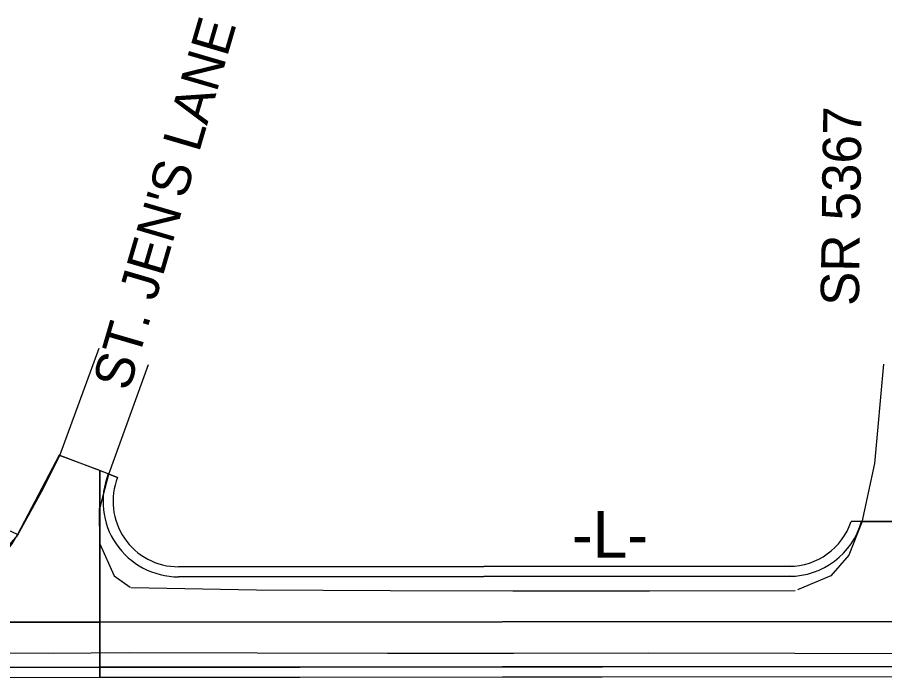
# Model space of a CAD drawing. Extents: x 2105791 to 2114488, y 667759 to 673441.
# Drawn here: x 2112480 to 2113084, y 670501 to 670961 of the extents above; entities that cross this region are included whole.
import ezdxf

# ---------------------------------------------------------------- set-up
doc = ezdxf.new("R2010")
doc.units = 0
for name, color, linetype in [('Exist Roads EOP', 7, 'Continuous'), ('Old_Level_1', 7, 'Continuous'), ('Prop EOT', 7, 'Continuous'), ('Prop Horizontal Alignment', 7, 'Continuous'), ('Prop Paved Shoulder', 7, 'Continuous'), ('Prop Shade Light', 7, 'Continuous')]:
    doc.layers.add(name, color=color, linetype=linetype)

msp = doc.modelspace()

# ---------------------------------------------------------------- linework, layer by layer
at = {"layer": 'Exist Roads EOP'}
for points in [[(2112536.43, 670730.29), (2112508.84, 670655.53), (2112496.29, 670630.73), (2112479.68, 670600.25), (2112452.98, 670569.69), (2112441.53, 670562.44)], [(2112570.66, 670719.08), (2112543.07, 670642.63), (2112536.77, 670618.71), (2112537.07, 670594.37), (2112546.95, 670571.87), (2112558.04, 670564.12)], [(2113083.05, 670719.57), (2113076.75, 670650.17), (2113067.96, 670609.35), (2113058.84, 670586.27), (2113046.36, 670571.99), (2113023.17, 670562.21)], [(2112558.52, 670563.78), (2112646.2, 670562.17), (2112739.32, 670561.73), (2112824.81, 670561.53), (2112919.99, 670561.59), (2113021.45, 670561.81)], [(2112231.19, 670513.92), (2112247.63, 670517.75), (2112319.83, 670518.16), (2112407.44, 670518.23), (2112504.55, 670518.1), (2112557.45, 670518.47), (2112646.65, 670518.39), (2112737.56, 670518.17), (2112825.34, 670518.17), (2112919.34, 670518.21), (2113021.28, 670518.03), (2113096.8, 670517.86), (2113173.07, 670517.66)]]:
    msp.add_lwpolyline(points, dxfattribs=at)
at = {"layer": 'Prop EOT'}
for p, q in [((2112508.7, 670656.04), (2112479.54, 670600.77)), ((2112542.92, 670643.14), (2112508.7, 670656.04)), ((2113067.82, 670609.84), (2113132.62, 670609.89)), ((2112591.77, 670571.28), (2113017.34, 670571.62)), ((2112229.9, 670507.99), (2113182.43, 670508.76))]:
    msp.add_line(p, q, dxfattribs=at)
for centre, start, end in [((2112591.73, 670623.78), 158.36737, 270.04585), ((2113017.3, 670624.12), 270.04586, 344.21029), ((2112432.29, 670623.66), 270.04586, 334.15022)]:
    msp.add_arc(centre, 52.5, start, end, dxfattribs=at)
at = {"layer": 'Prop Horizontal Alignment'}
msp.add_line((2111105.82, 670538.59), (2114200.25, 670541.07), dxfattribs=at)
at = {"layer": 'Prop Paved Shoulder'}
for p, q in [((2112542.92, 670643.14), (2112549.43, 670640.56)), ((2113067.82, 670609.84), (2113060.49, 670609.83)), ((2112479.54, 670600.77), (2112473.24, 670603.82)), ((2112591.76, 670578.28), (2113017.33, 670578.62)), ((2112229.91, 670500.99), (2113812.44, 670502.26))]:
    msp.add_line(p, q, dxfattribs=at)
for centre, start, end in [((2112591.73, 670623.78), 158.36737, 270.04585), ((2113017.3, 670624.12), 270.04586, 341.69358)]:
    msp.add_arc(centre, 45.5, start, end, dxfattribs=at)
at = {"layer": 'Prop Shade Light'}
for p, q in [((2112508.99, 670655.93), (2112508.84, 670655.53)), ((2112508.99, 670655.93), (2112508.84, 670655.53)), ((2112537.13, 670645.32), (2112508.99, 670655.93)), ((2112537.13, 670645.32), (2112508.99, 670655.93)), ((2112542.92, 670643.14), (2112537.13, 670645.32)), ((2112537.13, 670645.32), (2112537.13, 670539.74)), ((2112537.13, 670628.91), (2112537.13, 670645.32)), ((2112542.92, 670643.14), (2112537.13, 670645.32)), ((2112537.13, 670645.32), (2112537.13, 670539.74)), ((2112537.13, 670628.91), (2112537.13, 670645.32)), ((2112549.43, 670640.56), (2112542.92, 670643.14)), ((2112549.43, 670640.56), (2112542.92, 670643.14)), ((2112537.13, 670620.08), (2112537.13, 670628.91)), ((2112537.13, 670620.08), (2112537.13, 670628.91)), ((2113067.82, 670609.84), (2113060.49, 670609.83)), ((2113067.82, 670609.84), (2113060.49, 670609.83)), ((2113132.62, 670609.89), (2113067.82, 670609.84)), ((2113132.62, 670609.89), (2113067.82, 670609.84)), ((2112479.54, 670600.77), (2112473.24, 670603.82)), ((2112479.54, 670600.77), (2112473.24, 670603.82)), ((2112537.13, 670539.74), (2112537.13, 670594.23)), ((2112537.13, 670539.74), (2112537.13, 670594.23)), ((2113017.33, 670578.62), (2112591.76, 670578.28)), ((2113017.33, 670578.62), (2112591.76, 670578.28)), ((2112591.77, 670571.28), (2113017.34, 670571.62)), ((2113017.34, 670571.62), (2112591.77, 670571.28)), ((2112591.77, 670571.28), (2113017.34, 670571.62)), ((2113017.34, 670571.62), (2112591.77, 670571.28)), ((2112537.13, 670539.74), (2112065.91, 670539.36)), ((2112065.91, 670539.36), (2112537.13, 670539.74)), ((2112537.13, 670539.74), (2112065.91, 670539.36)), ((2112065.91, 670539.36), (2112537.13, 670539.74)), ((2112537.13, 670539.74), (2113811.57, 670540.76)), ((2113811.57, 670540.76), (2112537.13, 670539.74)), ((2112537.13, 670539.74), (2113811.57, 670540.76)), ((2113811.57, 670540.76), (2112537.13, 670539.74)), ((2112537.13, 670508.24), (2112537.13, 670539.74)), ((2112537.13, 670539.74), (2112537.13, 670508.24)), ((2112537.13, 670508.24), (2112537.13, 670539.74)), ((2112537.13, 670539.74), (2112537.13, 670508.24)), ((2112537.13, 670508.24), (2112229.9, 670507.99)), ((2112229.9, 670507.99), (2112537.13, 670508.24)), ((2112537.13, 670508.24), (2112229.9, 670507.99)), ((2112229.9, 670507.99), (2112537.13, 670508.24)), ((2112537.13, 670508.24), (2113182.43, 670508.76)), ((2113182.43, 670508.76), (2112537.13, 670508.24)), ((2112537.13, 670508.24), (2113182.43, 670508.76)), ((2113182.43, 670508.76), (2112537.13, 670508.24)), ((2112537.13, 670501.24), (2112537.13, 670508.24)), ((2112537.13, 670508.24), (2112537.13, 670501.24)), ((2112537.13, 670501.24), (2112537.13, 670508.24)), ((2112537.13, 670508.24), (2112537.13, 670501.24)), ((2112229.91, 670500.99), (2112537.13, 670501.24)), ((2112229.91, 670500.99), (2112537.13, 670501.24)), ((2112537.13, 670501.24), (2113812.44, 670502.26)), ((2112537.13, 670501.24), (2113812.44, 670502.26))]:
    msp.add_line(p, q, dxfattribs=at)
for points in [[(2112508.84, 670655.53), (2112496.29, 670630.73), (2112491.14, 670621.27)], [(2112508.84, 670655.53), (2112496.29, 670630.73), (2112491.14, 670621.27)], [(2112491.14, 670621.27), (2112479.68, 670600.25), (2112478.72, 670599.15)], [(2112491.14, 670621.27), (2112479.68, 670600.25), (2112478.72, 670599.15)], [(2112537.13, 670594.23), (2112537.07, 670594.37), (2112536.77, 670618.71), (2112537.13, 670620.08)], [(2112537.13, 670594.23), (2112537.07, 670594.37), (2112536.77, 670618.71), (2112537.13, 670620.08)]]:
    msp.add_lwpolyline(points, dxfattribs=at)
for centre, radius, start, end in [((2112591.73, 670623.78), 52.5, 158.36737, 270.04585), ((2112591.73, 670623.78), 52.5, 158.36737, 270.04585), ((2112591.73, 670623.78), 52.5, 158.36737, 270.04585), ((2112591.73, 670623.78), 52.5, 158.36737, 270.04585), ((2112591.73, 670623.78), 45.5, 158.36737, 270.04585), ((2112591.73, 670623.78), 45.5, 158.36737, 270.04585), ((2113017.3, 670624.12), 45.5, 270.04586, 341.69358), ((2113017.3, 670624.12), 45.5, 270.04586, 341.69358), ((2113017.3, 670624.12), 52.5, 270.04586, 344.21029), ((2113017.3, 670624.12), 52.5, 270.04586, 344.21029), ((2113017.3, 670624.12), 52.5, 270.04586, 344.21029), ((2113017.3, 670624.12), 52.5, 270.04586, 344.21029), ((2112432.29, 670623.66), 52.5, 270.04586, 334.15022), ((2112432.29, 670623.66), 52.5, 270.04586, 334.15022)]:
    msp.add_arc(centre, radius, start, end, dxfattribs=at)

# ---------------------------------------------------------------- texts
at = {"layer": 'Old_Level_1'}
for s, height, rotation, p in [("ST. JEN'S LANE", 26.6957, 73.67098, (2112557.29, 670699.92)), ('SR 5367  ', 26.696, 89.19717, (2113065.95, 670759.97)), ('-L-', 32.551, 360, (2112865.92, 670584.56))]:
    msp.add_text(s, height=height, rotation=rotation, dxfattribs=at).set_placement(p)

doc.saveas('drawing.dxf')
